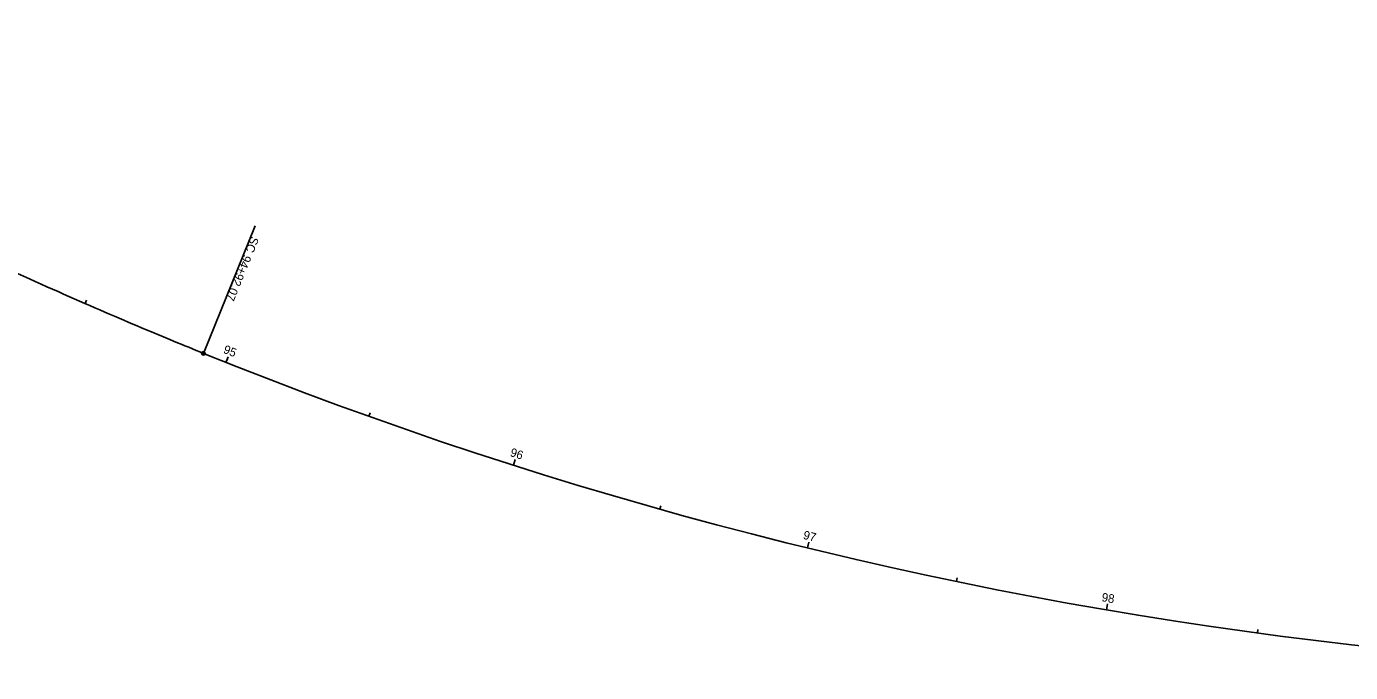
# Model space of a CAD drawing. Extents: x 1999336 to 2003366, y 252766 to 253936.
# Drawn here: x 2002043.7 to 2002477.2, y 252766.1 to 252977.6 of the extents above; entities that cross this region are included whole.
import ezdxf

# ---------------------------------------------------------------- set-up
doc = ezdxf.new("R2010")
doc.units = 0
for name, color, linetype in [('GE_X_CL_20', 7, 'Continuous'), ('GK_Visualization', 7, 'Continuous'), ('SC_Scratch3', 7, 'Continuous'), ('SV_X_Text_Name', 7, 'Continuous')]:
    doc.layers.add(name, color=color, linetype=linetype)

msp = doc.modelspace()

# ---------------------------------------------------------------- linework, layer by layer
at = {"layer": 'GE_X_CL_20'}
for p, q in [((2002101.69, 252870.61), (2002118.56, 252912.32)), ((2002109.05, 252867.65), (2002109.79, 252869.51)), ((2002203.18, 252833.94), (2002203.54, 252835.09)), ((2002299.42, 252806.88), (2002299.71, 252808.05)), ((2002397.32, 252786.6), (2002397.53, 252787.78))]:
    msp.add_line(p, q, dxfattribs=at)
msp.add_circle((2002101.69, 252870.61), 0.6, dxfattribs=at)
at = {"layer": 'GK_Visualization'}
msp.add_arc((2002638.78, 254198.49), 1432.39, 247.97811, 278.15308, dxfattribs=at)
msp.add_arc((2002638.78, 254198.49), 1432.39, 247.97811, 278.15308, dxfattribs=at)
msp.add_open_spline([(2001875.85, 252977.63), (2001882.03, 252974.47), (2001894.41, 252968.16), (2001919.17, 252955.57), (2001950.18, 252939.95), (2001987.57, 252921.56), (2002025.22, 252903.72), (2002056.88, 252889.46), (2002082.41, 252878.51), (2002095.25, 252873.21), (2002101.69, 252870.61)], degree=3, dxfattribs=at)
msp.add_open_spline([(2001875.85, 252977.63), (2001882.03, 252974.47), (2001894.41, 252968.16), (2001919.17, 252955.57), (2001950.18, 252939.95), (2001987.57, 252921.56), (2002025.22, 252903.72), (2002056.88, 252889.46), (2002082.41, 252878.51), (2002095.25, 252873.21), (2002101.69, 252870.61)], degree=3, dxfattribs=at)
at = {"layer": 'SC_Scratch3'}
for p, q in [((2002101.69, 252870.61), (2002118.56, 252912.32)), ((2002062.91, 252886.92), (2002063.39, 252888.02)), ((2002109.05, 252867.65), (2002109.79, 252869.51)), ((2002155.82, 252849.98), (2002156.22, 252851.11)), ((2002203.18, 252833.94), (2002203.78, 252835.85)), ((2002251.06, 252819.57), (2002251.39, 252820.73)), ((2002299.42, 252806.88), (2002299.9, 252808.82)), ((2002348.2, 252795.89), (2002348.44, 252797.06)), ((2002397.32, 252786.6), (2002397.66, 252788.57)), ((2002446.75, 252779.03), (2002446.91, 252780.22))]:
    msp.add_line(p, q, dxfattribs=at)
msp.add_circle((2002101.69, 252870.61), 0.6, dxfattribs=at)
at = {"layer": 'SV_X_Text_Name'}
for p, q in [((2002101.69, 252870.61), (2002118.56, 252912.32)), ((2002109.05, 252867.65), (2002109.5, 252868.77))]:
    msp.add_line(p, q, dxfattribs=at)
msp.add_circle((2002101.69, 252870.61), 0.6, dxfattribs=at)

# ---------------------------------------------------------------- texts
at = {"layer": 'GE_X_CL_20'}
for s, rotation, p in [('SC', 247.9781, (2002117.31, 252909.11)), ('94+92.07', 247.9781, (2002114.86, 252903.06)), ('95', 338.2955, (2002107.94, 252870.84))]:
    msp.add_text(s, height=2.8, rotation=rotation, dxfattribs=at).set_placement(p)
at = {"layer": 'SC_Scratch3'}
for s, rotation, p in [('SC', 247.9781, (2002117.31, 252909.11)), ('94+92.07', 247.9781, (2002114.86, 252903.06)), ('95', 338.2955, (2002107.94, 252870.84)), ('96', 342.2955, (2002201.86, 252837.04)), ('97', 346.2955, (2002297.84, 252809.89)), ('98', 350.2955, (2002395.59, 252789.48))]:
    msp.add_text(s, height=2.8, rotation=rotation, dxfattribs=at).set_placement(p)
at = {"layer": 'SV_X_Text_Name'}
for s, p in [('SC', (2002117.31, 252909.11)), ('94+92.07', (2002114.86, 252903.06))]:
    msp.add_text(s, height=2.8, rotation=247.9781, dxfattribs=at).set_placement(p)

doc.saveas('drawing.dxf')
